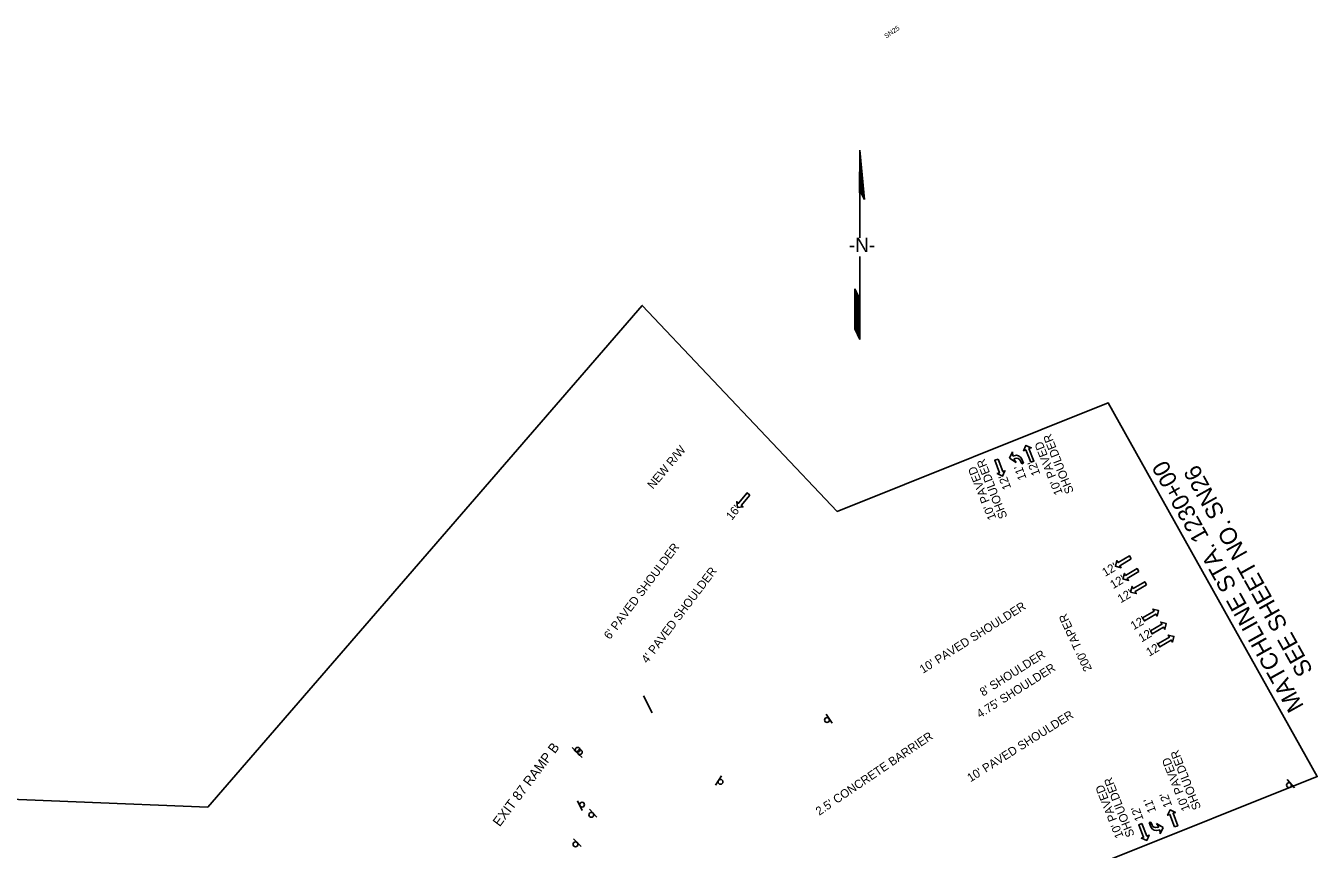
# Model space of a CAD drawing. Extents: x 1770940 to 1772558, y 1178099 to 1179642.
# Drawn here: x 1771494 to 1772558, y 1178963 to 1179642 of the extents above; entities that cross this region are included whole.
import ezdxf

# ---------------------------------------------------------------- set-up
doc = ezdxf.new("R2010")
doc.units = 0
for name, color, linetype in [('RD_PD_Final_LnLine', 7, 'Continuous'), ('RD_PD_Final_TX', 7, 'Continuous'), ('RD_PD_RW_TX', 7, 'Continuous'), ('RD_SHT_MatchLine', 7, 'Continuous'), ('RD_SHT_ShtClip', 7, 'Continuous'), ('RD_SHT_TX', 7, 'Continuous'), ('RD_Sketch1', 7, 'Continuous'), ('RD_TX_RoadID', 7, 'Continuous'), ('SN_P_Signs', 7, 'Continuous')]:
    doc.layers.add(name, color=color, linetype=linetype)

# ---------------------------------------------------------------- blocks, each defined once
blk = doc.blocks.new('NA5')
at = {"layer": 'RD_Sketch1'}
for p, q in [((47.5, 65.9), (26.8, 37.4)), ((26.8, 30.6), (47.5, 65.9)), ((27.2, 37.5), (14.5, 19.8)), ((28.1, 38.3), (26.8, 30.6)), ((14.5, 19.8), (5.5, 7.2)), ((-3.5, -5.3), (-18.5, -26.3)), ((-18.5, -26.3), (-43.3, -60.9)), ((-30.6, -36.2), (-22.3, -24.7)), ((-22.3, -24.7), (-24, -34)), ((-41.6, -51.6), (-30.6, -36.2)), ((-43.3, -60.9), (-41.6, -51.6))]:
    blk.add_line(p, q, dxfattribs=at)
for points in [[(27.4, 37.8), (47.4, 65.8)], [(27.6, 37.9), (46.9, 64.9)], [(27.8, 38.1), (46.4, 64)], [(27.1, 37.6), (39.2, 54.5)], [(27.7, 36.2), (40.6, 54.2)], [(27.7, 36), (40.1, 53.3)], [(27.8, 36.8), (42.2, 56.8)], [(27.8, 36.6), (41.7, 56)], [(27.8, 36.4), (41.1, 55.1)], [(27.9, 37.4), (43.8, 59.5)], [(27.9, 37.2), (43.2, 58.6)], [(27.9, 37), (42.7, 57.7)], [(28, 38.1), (45.3, 62.2)], [(28, 37.9), (44.8, 61.3)], [(28, 37.7), (44.3, 60.4)], [(28.1, 38.3), (45.8, 63.1)], [(27.3, 33.9), (34.8, 44.3)], [(27.3, 33.7), (34.3, 43.4)], [(27.4, 34.5), (36.4, 47)], [(27.4, 34.3), (35.9, 46.1)], [(27.4, 34.1), (35.4, 45.2)], [(27.5, 34.9), (37.5, 48.8)], [(27.5, 34.7), (36.9, 47.9)], [(27.6, 35.5), (39, 51.5)], [(27.6, 35.3), (38.5, 50.6)], [(27.6, 35.1), (38, 49.7)], [(27.7, 35.8), (39.6, 52.4)], [(26.9, 37.5), (29.9, 41.7)], [(26.9, 31.3), (28.5, 33.6)], [(26.9, 31.1), (28, 32.7)], [(27, 32), (30.1, 36.3)], [(27, 31.8), (29.6, 35.4)], [(27, 31.5), (29.1, 34.5)], [(27.1, 32.6), (31.7, 39)], [(27.1, 32.4), (31.2, 38.1)], [(27.1, 32.2), (30.6, 37.2)], [(27.2, 33.2), (33.3, 41.6)], [(27.2, 33), (32.7, 40.7)], [(27.2, 32.8), (32.2, 39.9)], [(27.3, 33.4), (33.8, 42.5)], [(26.8, 30.7), (27, 30.9)], [(26.9, 30.9), (27.5, 31.8)], [(-42.9, -58.6), (-23.6, -31.7)], [(-42.9, -58.8), (-23.7, -31.9)], [(-42.8, -58.1), (-23.5, -31.2)], [(-42.8, -58.3), (-23.6, -31.4)], [(-42.7, -57.5), (-23.4, -30.6)], [(-42.7, -57.7), (-23.5, -30.8)], [(-42.7, -57.9), (-23.5, -31)], [(-42.6, -57), (-23.3, -30.1)], [(-42.6, -57.2), (-23.4, -30.4)], [(-42.5, -56.4), (-23.2, -29.5)], [(-42.5, -56.6), (-23.2, -29.7)], [(-42.5, -56.8), (-23.3, -29.9)], [(-42.4, -55.9), (-23.1, -29)], [(-42.4, -56.1), (-23.2, -29.3)], [(-42.3, -55.3), (-23, -28.4)], [(-42.3, -55.5), (-23, -28.6)], [(-42.3, -55.7), (-23.1, -28.8)], [(-42.2, -54.8), (-22.9, -27.9)], [(-42.2, -55), (-23, -28.2)], [(-42.1, -54.4), (-22.8, -27.5)], [(-42.1, -54.6), (-22.9, -27.7)], [(-42, -53.7), (-22.7, -26.8)], [(-42, -53.9), (-22.7, -27.1)], [(-42, -54.2), (-22.8, -27.3)], [(-41.9, -53.3), (-22.6, -26.4)], [(-41.9, -53.5), (-22.7, -26.6)], [(-41.8, -52.6), (-22.5, -25.7)], [(-41.8, -52.8), (-22.5, -26)], [(-41.8, -53.1), (-22.6, -26.2)], [(-41.7, -52.2), (-22.4, -25.3)], [(-41.7, -52.4), (-22.5, -25.5)], [(-41.6, -51.7), (-22.3, -24.9)], [(-41.6, -52), (-22.4, -25.1)], [(-43.3, -60.8), (-24, -33.9)], [(-43.2, -60.1), (-23.9, -33.2)], [(-43.2, -60.3), (-23.9, -33.4)], [(-43.2, -60.5), (-24, -33.6)], [(-43.1, -59.7), (-23.8, -32.8)], [(-43.1, -59.9), (-23.9, -33)], [(-43, -59), (-23.7, -32.1)], [(-43, -59.2), (-23.7, -32.3)], [(-43, -59.4), (-23.8, -32.5)]]:
    blk.add_lwpolyline(points, dxfattribs=at)
blk.add_text('-N-', height=11.81, rotation=324.3865, dxfattribs=at).set_placement((-8.8, 3))
blk = doc.blocks.new('SARRW2')
at = {"layer": 'RD_PD_Final_LnLine'}
blk.add_lwpolyline([(-12, 1.2), (-12, -1.2), (-2.83, -1.2), (-2.83, -2.83), (0, 0), (-2.83, 2.83), (-2.83, 1.2)], close=True, dxfattribs=at)

msp = doc.modelspace()

# ---------------------------------------------------------------- linework, layer by layer
at = {"layer": 'RD_PD_Final_TX'}
for p, q in [((1772306.9, 1179290.9), (1772304.3, 1179285.7)), ((1772304.3, 1179285.7), (1772309.9, 1179282.2)), ((1772307.1, 1179287.4), (1772306.9, 1179290.9)), ((1772308.1, 1179287.8), (1772307.1, 1179287.4)), ((1772308, 1179285.1), (1772309.1, 1179285.5)), ((1772309.9, 1179282.2), (1772308, 1179285.1)), ((1772313.5, 1179283.6), (1772314.5, 1179281.1)), ((1772315.9, 1179281.6), (1772314.5, 1179285.1)), ((1772314.5, 1179281.1), (1772315.9, 1179281.6)), ((1772421, 1178985.8), (1772419.6, 1178985.3)), ((1772419.6, 1178985.3), (1772421, 1178981.8)), ((1772422, 1178983.3), (1772421, 1178985.8)), ((1772431.2, 1178981.2), (1772425.6, 1178984.7)), ((1772425.6, 1178984.7), (1772427.4, 1178981.8)), ((1772427.4, 1178981.8), (1772426.4, 1178981.4)), ((1772427.3, 1178979.1), (1772428.3, 1178979.5)), ((1772428.3, 1178979.5), (1772428.6, 1178976)), ((1772428.6, 1178976), (1772431.2, 1178981.2))]:
    msp.add_line(p, q, dxfattribs=at)
for centre, radius, start, end in [((1772310, 1179283.3), 4.88, 21.825, 111.825), ((1772310.3, 1179282.4), 3.38, 21.825, 111.825), ((1772425.5, 1178983.6), 4.88, 201.825, 291.825), ((1772425.1, 1178984.6), 3.38, 201.825, 291.825)]:
    msp.add_arc(centre, radius, start, end, dxfattribs=at)
at = {"layer": 'RD_SHT_MatchLine'}
msp.add_lwpolyline([(1772558.1, 1179023.3), (1772385.8, 1179331.3)], dxfattribs=at)
at = {"layer": 'RD_SHT_ShtClip'}
msp.add_lwpolyline([(1771296.2, 1178245.5), (1771109.1, 1178512.4), (1770940, 1178753.7), (1771317.8, 1179011.2), (1771643.5, 1178998.1), (1772001.7, 1179411.7), (1772162.5, 1179241.9), (1772385.8, 1179331.3), (1772558.1, 1179023.3), (1772212.5, 1178884.9), (1772278.1, 1178588), (1772022.9, 1178414.1), (1771928, 1178222.3), (1771398.9, 1178099.1)], close=True, dxfattribs=at)
at = {"layer": 'SN_P_Signs'}
for p, q in [((1772010, 1179075.8), (1772002.6, 1179089.9)), ((1772158.2, 1179067.3), (1772153.2, 1179074.7)), ((1771943.9, 1179047.4), (1771949.9, 1179040.7)), ((1771945.7, 1179045.1), (1771952.2, 1179039)), ((1772066.9, 1179023.9), (1772062.1, 1179016.3)), ((1772539.3, 1179014.1), (1772533.4, 1179020.9)), ((1771948.4, 1179003.4), (1771952.2, 1178995.2)), ((1771964.2, 1178989.7), (1771958.2, 1178996.4)), ((1771951.4, 1178965.7), (1771944.9, 1178972))]:
    msp.add_line(p, q, dxfattribs=at)
for centre in [(1772154, 1179069.9), (1771948.5, 1179045.4), (1771950.3, 1179043.5), (1772066.2, 1179019), (1772534.8, 1179016.2), (1771952.1, 1179000.1), (1771959.7, 1178991.7), (1771946.7, 1178967.4)]:
    msp.add_circle(centre, 2, dxfattribs=at)

# ---------------------------------------------------------------- block references
at = {"layer": 'RD_PD_Final_LnLine'}
for p, xscale, yscale, rotation in [((1772317.9, 1179296.3), 1.2000000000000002, 1.2000000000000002, 111.72003018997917), ((1772298.7, 1179271.1), 1.1999999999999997, 1.2000000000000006, -69.5555201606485), ((1772080.1, 1179245.1), 1.1999999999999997, 1.2000000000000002, -129.02430529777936), ((1772391.7, 1179196.7), 1.2, 1.2000000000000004, -149.51993123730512), ((1772397.9, 1179186.2), 1.2, 1.2000000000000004, -149.51993123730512), ((1772404.3, 1179175.4), 1.2, 1.2000000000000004, -149.51993123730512), ((1772427.3, 1179160.2), 1.1999999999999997, 1.2000000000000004, 30.480068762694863), ((1772433.7, 1179149.4), 1.1999999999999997, 1.2000000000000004, 30.480068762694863), ((1772439.9, 1179138.8), 1.1999999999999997, 1.2000000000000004, 30.480068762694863), ((1772436.8, 1178995.8), 1.1999999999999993, 1.2, 110.4444798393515), ((1772417.6, 1178970.6), 1.1999999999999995, 1.2, -68.27996981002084)]:
    msp.add_blockref('SARRW2', p, dxfattribs=dict(at, xscale=xscale, yscale=yscale, rotation=rotation))
at = {"layer": 'RD_SHT_MatchLine', "rotation": 35.61349782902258}
msp.add_blockref('NA5', (1772180.8, 1179458.5), dxfattribs=at)

# ---------------------------------------------------------------- texts
at = {"layer": 'RD_PD_Final_TX'}
for s, rotation, p in [("10' PAVED", 111.6042, (1772348.4, 1179257.1)), ('SHOULDER', 111.6042, (1772357.6, 1179258.1)), ("10' PAVED", 111.6042, (1772293.6, 1179236.5)), ('SHOULDER', 111.6042, (1772302.8, 1179237.5)), ("11'", 110.4445, (1772318.6, 1179269.2)), ("12'", 110.4445, (1772329.9, 1179272.8)), ("12'", 110.4445, (1772305.9, 1179261.3)), ("16'", 50.9757, (1772075.5, 1179234.1)), ("6' PAVED SHOULDER", 53.0311, (1771975, 1179135.8)), ("4' PAVED SHOULDER", 53.0311, (1772005.9, 1179116.1)), ("12'", 30.4801, (1772383.3, 1179187.9)), ("12'", 30.4801, (1772389.9, 1179177.8)), ("12'", 30.4801, (1772396.1, 1179166.1)), ("10' PAVED SHOULDER", 32.2635, (1772233.1, 1179108)), ("200' TAPER", 114.8811, (1772372.6, 1179111.9)), ("12'", 30.4801, (1772406.8, 1179143.9)), ("12'", 30.4801, (1772413.3, 1179133.8)), ("8' SHOULDER", 32.4975, (1772282.7, 1179089.2)), ("12'", 30.4801, (1772419.6, 1179122.1)), ("4.75' SHOULDER", 32.4975, (1772280.1, 1179071.2)), ("10' PAVED SHOULDER", 32.2184, (1772272.3, 1179018.5)), ("2.5' CONCRETE BARRIER", 34.1587, (1772147.6, 1178990.9)), ('SHOULDER', 111.6042, (1772462.5, 1178997.5)), ("10' PAVED", 111.6042, (1772453.4, 1178996.5)), ('SHOULDER', 111.6042, (1772407.7, 1178975)), ("10' PAVED", 111.6042, (1772398.6, 1178974)), ("11'", 110.4445, (1772425.4, 1178994.8)), ("12'", 110.4445, (1772438.6, 1178999.3)), ("12'", 110.4445, (1772415.1, 1178988))]:
    msp.add_text(s, height=7, rotation=rotation, dxfattribs=at).set_placement(p)
at = {"layer": 'RD_PD_RW_TX'}
msp.add_text('NEW R/W', height=7, rotation=50.0262, dxfattribs=at).set_placement((1772010.6, 1179259.8))
at = {"layer": 'RD_SHT_MatchLine'}
for s, p in [('MATCHLINE STA. 1230+00', (1772547.4, 1179081.3)), ('SEE SHEET NO. SN26', (1772555, 1179110.7))]:
    msp.add_text(s, height=14, rotation=119.216, dxfattribs=at).set_placement(p)
at = {"layer": 'RD_SHT_TX'}
msp.add_text('SN25', height=4, rotation=34.2793, dxfattribs=at).set_placement((1772202.9, 1179631.7))
at = {"layer": 'RD_TX_RoadID'}
msp.add_text('EXIT 87 RAMP B', height=8, rotation=53.026, dxfattribs=at).set_placement((1771884.2, 1178981.4))

doc.saveas('drawing.dxf')
